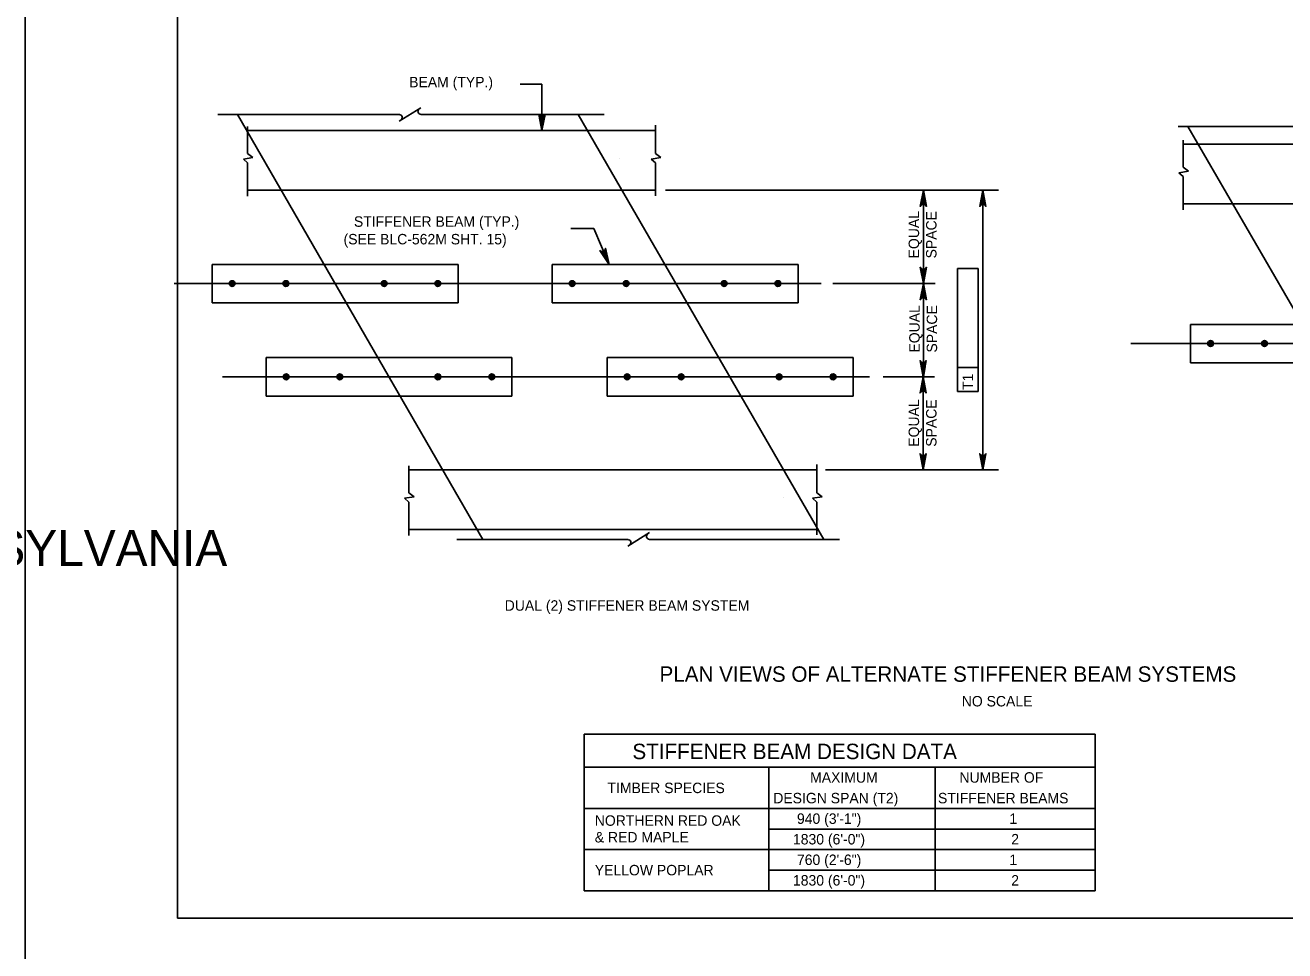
# Model space of a CAD drawing. Extents: x -13 to 81, y -176 to 0.
# Drawn here: x 34 to 48.46, y -131.62 to -121 of the extents above; entities that cross this region are included whole.
import ezdxf

# ---------------------------------------------------------------- set-up
doc = ezdxf.new("R2010")
doc.units = 0
for name, color, linetype in [('Level 1', 7, 'Continuous'), ('Level 10', 7, 'Continuous'), ('Level 2', 7, 'Continuous'), ('Level 3', 7, 'Continuous'), ('Level 4', 7, 'Continuous'), ('Level 63', 7, 'Continuous'), ('Level 8', 7, 'Continuous')]:
    doc.layers.add(name, color=color, linetype=linetype)

msp = doc.modelspace()

# ---------------------------------------------------------------- linework, layer by layer
at = {"layer": 'Level 1'}
msp.add_lwpolyline([(35.75, -131.25), (67.25, -131.25), (67.25, -110.75), (35.75, -110.75)], close=True, dxfattribs=at)
at = {"layer": 'Level 10'}
for p, q in [((40.418, -129.137), (40.418, -130.935)), ((40.418, -129.137), (46.284, -129.137)), ((46.284, -129.137), (46.284, -130.935)), ((40.418, -129.518), (46.284, -129.518)), ((42.537, -129.518), (42.537, -130.935)), ((44.448, -129.518), (44.448, -130.935)), ((40.418, -129.991), (46.284, -129.991)), ((42.537, -130.227), (46.284, -130.227)), ((40.418, -130.463), (46.284, -130.463)), ((42.537, -130.699), (46.284, -130.699)), ((40.418, -130.935), (46.284, -130.935))]:
    msp.add_line(p, q, dxfattribs=at)
at = {"layer": 'Level 2'}
for p, q in [((36.436, -122.025), (39.255, -126.903)), ((40.349, -122.025), (43.169, -126.903)), ((47.349, -122.161), (50.221, -127.129))]:
    msp.add_line(p, q, dxfattribs=at)
at = {"layer": 'Level 3'}
for p, q in [((38.296, -122.025), (36.213, -122.025)), ((38.542, -121.947), (38.295, -122.102)), ((40.646, -122.025), (38.544, -122.025)), ((36.554, -122.471), (36.554, -122.162)), ((41.237, -122.471), (41.237, -122.148)), ((49.318, -122.161), (47.235, -122.161)), ((41.237, -122.21), (36.554, -122.21)), ((47.292, -122.628), (47.292, -122.319)), ((36.615, -122.519), (36.554, -122.471)), ((41.298, -122.519), (41.237, -122.471)), ((51.975, -122.367), (47.292, -122.367)), ((36.505, -122.536), (36.615, -122.519)), ((36.554, -122.58), (36.505, -122.536)), ((36.554, -122.964), (36.554, -122.58)), ((41.188, -122.536), (41.298, -122.519)), ((41.237, -122.58), (41.188, -122.536)), ((41.237, -122.957), (41.237, -122.58)), ((47.244, -122.693), (47.354, -122.676)), ((47.292, -122.737), (47.244, -122.693)), ((47.354, -122.676), (47.292, -122.628)), ((47.292, -123.121), (47.292, -122.737)), ((36.554, -122.895), (41.237, -122.895)), ((47.292, -123.052), (51.975, -123.052)), ((38.969, -123.746), (36.146, -123.746)), ((36.146, -123.746), (36.146, -124.187)), ((38.969, -123.746), (38.969, -124.187)), ((42.872, -123.746), (40.049, -123.746)), ((40.049, -123.746), (40.049, -124.187)), ((42.872, -123.746), (42.872, -124.187)), ((41.464, -123.965), (41.464, -123.965)), ((38.969, -124.187), (36.146, -124.187)), ((42.872, -124.187), (40.049, -124.187)), ((50.201, -124.434), (47.378, -124.434)), ((47.378, -124.434), (47.378, -124.875)), ((39.588, -124.816), (36.765, -124.816)), ((36.765, -124.816), (36.765, -125.257)), ((39.588, -124.816), (39.588, -125.257)), ((40.682, -124.816), (40.682, -125.257)), ((43.505, -124.816), (40.682, -124.816)), ((43.505, -124.816), (43.505, -125.257)), ((50.201, -124.875), (47.378, -124.875)), ((42.096, -125.035), (42.096, -125.035)), ((39.588, -125.257), (36.765, -125.257)), ((43.505, -125.257), (40.682, -125.257)), ((38.405, -126.367), (38.405, -126.058)), ((43.088, -126.367), (43.088, -126.043)), ((43.088, -126.105), (38.405, -126.105)), ((38.466, -126.414), (38.405, -126.367)), ((43.149, -126.414), (43.088, -126.367)), ((38.356, -126.431), (38.466, -126.414)), ((38.405, -126.475), (38.356, -126.431)), ((38.405, -126.859), (38.405, -126.475)), ((43.039, -126.431), (43.149, -126.414)), ((43.088, -126.475), (43.039, -126.431)), ((43.088, -126.852), (43.088, -126.475)), ((38.405, -126.79), (43.088, -126.79)), ((40.92, -126.903), (38.954, -126.903)), ((41.166, -126.825), (40.92, -126.98)), ((43.348, -126.903), (41.169, -126.903))]:
    msp.add_line(p, q, dxfattribs=at)
for centre, radius in [((36.376, -123.966), 0.0333), ((36.376, -123.966), 0.0295), ((36.376, -123.966), 0.025), ((36.376, -123.966), 0.0167), ((36.376, -123.966), 0.00833), ((36.994, -123.966), 0.0333), ((36.994, -123.966), 0.0295), ((36.994, -123.966), 0.025), ((36.994, -123.966), 0.0167), ((36.994, -123.966), 0.00833), ((38.12, -123.966), 0.0333), ((38.12, -123.966), 0.0295), ((38.12, -123.966), 0.025), ((38.12, -123.966), 0.0167), ((38.12, -123.966), 0.00833), ((38.738, -123.966), 0.0333), ((38.738, -123.966), 0.0295), ((38.738, -123.966), 0.025), ((38.738, -123.966), 0.0167), ((38.738, -123.966), 0.00833), ((40.28, -123.966), 0.0333), ((40.28, -123.966), 0.0295), ((40.28, -123.966), 0.025), ((40.28, -123.966), 0.0167), ((40.28, -123.966), 0.00833), ((40.898, -123.966), 0.0333), ((40.898, -123.966), 0.0295), ((40.898, -123.966), 0.025), ((40.898, -123.966), 0.0167), ((40.898, -123.966), 0.00833), ((42.024, -123.966), 0.0333), ((42.024, -123.966), 0.0295), ((42.024, -123.966), 0.025), ((42.024, -123.966), 0.0167), ((42.024, -123.966), 0.00833), ((42.642, -123.966), 0.0333), ((42.642, -123.966), 0.0295), ((42.642, -123.966), 0.025), ((42.642, -123.966), 0.0167), ((42.642, -123.966), 0.00833), ((47.609, -124.654), 0.0333), ((47.609, -124.654), 0.0295), ((47.609, -124.654), 0.025), ((47.609, -124.654), 0.0167), ((47.609, -124.654), 0.00833), ((48.227, -124.654), 0.0333), ((48.227, -124.654), 0.0295), ((48.227, -124.654), 0.025), ((48.227, -124.654), 0.0167), ((48.227, -124.654), 0.00833), ((36.995, -125.036), 0.0333), ((36.995, -125.036), 0.0295), ((36.995, -125.036), 0.025), ((36.995, -125.036), 0.0167), ((36.995, -125.036), 0.00833), ((37.613, -125.036), 0.0333), ((37.613, -125.036), 0.0295), ((37.613, -125.036), 0.025), ((37.613, -125.036), 0.0167), ((37.613, -125.036), 0.00833), ((38.739, -125.036), 0.0333), ((38.739, -125.036), 0.0295), ((38.739, -125.036), 0.025), ((38.739, -125.036), 0.0167), ((38.739, -125.036), 0.00833), ((39.358, -125.036), 0.0333), ((39.358, -125.036), 0.0295), ((39.358, -125.036), 0.025), ((39.358, -125.036), 0.0167), ((39.358, -125.036), 0.00833), ((40.912, -125.036), 0.0333), ((40.912, -125.036), 0.0295), ((40.912, -125.036), 0.025), ((40.912, -125.036), 0.0167), ((40.912, -125.036), 0.00833), ((41.53, -125.036), 0.0333), ((41.53, -125.036), 0.0295), ((41.53, -125.036), 0.025), ((41.53, -125.036), 0.0167), ((41.53, -125.036), 0.00833), ((42.656, -125.036), 0.0333), ((42.656, -125.036), 0.0295), ((42.656, -125.036), 0.025), ((42.656, -125.036), 0.0167), ((42.656, -125.036), 0.00833), ((43.274, -125.036), 0.0333), ((43.274, -125.036), 0.0295), ((43.274, -125.036), 0.025), ((43.274, -125.036), 0.0167), ((43.274, -125.036), 0.00833)]:
    msp.add_circle(centre, radius, dxfattribs=at)
for centre, start, end in [((38.292, -122.061), 302.1328, 84.6714), ((38.545, -121.988), 120, 270), ((40.917, -126.939), 302.1328, 84.6714), ((41.169, -126.867), 120, 270)]:
    msp.add_arc(centre, 0.0364, start, end, dxfattribs=at)
at = {"layer": 'Level 4'}
for p, q in [((39.933, -121.677), (39.683, -121.677)), ((41.349, -122.895), (44.757, -122.895)), ((43.644, -122.895), (45.174, -122.895)), ((43.797, -122.895), (44.4, -122.895)), ((44.311, -122.895), (44.311, -123.965)), ((44.994, -122.895), (44.994, -126.105)), ((40.53, -123.333), (40.264, -123.333)), ((44.703, -123.793), (44.939, -123.793)), ((44.703, -124.906), (44.703, -123.793)), ((44.939, -123.793), (44.939, -125.205)), ((43.138, -123.965), (35.712, -123.965)), ((44.446, -123.965), (43.271, -123.965)), ((44.311, -123.965), (44.311, -124.917)), ((53.983, -124.654), (46.692, -124.654)), ((44.703, -125.205), (44.703, -124.906)), ((44.939, -124.93), (44.703, -124.93)), ((43.692, -125.036), (36.267, -125.036)), ((44.438, -125.035), (43.851, -125.035)), ((44.308, -125.153), (44.308, -126.105)), ((44.939, -125.205), (44.703, -125.205)), ((43.186, -126.105), (45.174, -126.105)), ((44.049, -126.105), (44.384, -126.105))]:
    msp.add_line(p, q, dxfattribs=at)
for points in [[(39.933, -122.21), (39.933, -121.677)], [(39.933, -122.21), (39.968, -122.024), (39.958, -122.038), (39.946, -122.045), (39.933, -122.048), (39.921, -122.045), (39.908, -122.038), (39.898, -122.024), (39.933, -122.21), (39.908, -122.038), (39.921, -122.045), (39.933, -122.21), (39.933, -122.048), (39.946, -122.045), (39.933, -122.21), (39.958, -122.038)], [(44.311, -122.895), (44.276, -123.081), (44.286, -123.067), (44.298, -123.06), (44.311, -123.057), (44.323, -123.06), (44.336, -123.067), (44.346, -123.081), (44.311, -122.895), (44.336, -123.067), (44.323, -123.06), (44.311, -122.895), (44.311, -123.057), (44.298, -123.06), (44.311, -122.895), (44.286, -123.067)], [(44.994, -122.895), (44.959, -123.081), (44.969, -123.067), (44.982, -123.06), (44.994, -123.057), (45.007, -123.06), (45.019, -123.067), (45.029, -123.081), (44.994, -122.895), (45.019, -123.067), (45.007, -123.06), (44.994, -122.895), (44.994, -123.057), (44.982, -123.06), (44.994, -122.895), (44.969, -123.067)], [(40.703, -123.746), (40.53, -123.333)], [(40.703, -123.746), (40.663, -123.56), (40.659, -123.578), (40.651, -123.589), (40.64, -123.596), (40.628, -123.599), (40.613, -123.597), (40.598, -123.587), (40.703, -123.746), (40.613, -123.597), (40.628, -123.599), (40.703, -123.746), (40.64, -123.596), (40.651, -123.589), (40.703, -123.746), (40.659, -123.578)], [(44.311, -123.965), (44.346, -123.779), (44.336, -123.793), (44.323, -123.8), (44.311, -123.803), (44.298, -123.8), (44.286, -123.793), (44.276, -123.779), (44.311, -123.965), (44.286, -123.793), (44.298, -123.8), (44.311, -123.965), (44.311, -123.803), (44.323, -123.8), (44.311, -123.965), (44.336, -123.793)], [(44.311, -123.965), (44.346, -124.151), (44.336, -124.137), (44.323, -124.13), (44.311, -124.128), (44.298, -124.13), (44.286, -124.137), (44.276, -124.151), (44.311, -123.965), (44.286, -124.137), (44.298, -124.13), (44.311, -123.965), (44.311, -124.128), (44.323, -124.13), (44.311, -123.965), (44.336, -124.137)], [(44.308, -125.035), (44.343, -124.849), (44.334, -124.863), (44.321, -124.87), (44.308, -124.873), (44.296, -124.87), (44.283, -124.863), (44.274, -124.849), (44.308, -125.035), (44.283, -124.863), (44.296, -124.87), (44.308, -125.035), (44.308, -124.873), (44.321, -124.87), (44.308, -125.035), (44.334, -124.863)], [(44.308, -125.035), (44.343, -125.222), (44.334, -125.207), (44.321, -125.2), (44.308, -125.198), (44.296, -125.2), (44.283, -125.207), (44.274, -125.222), (44.308, -125.035), (44.283, -125.207), (44.296, -125.2), (44.308, -125.035), (44.308, -125.198), (44.321, -125.2), (44.308, -125.035), (44.334, -125.207)], [(44.308, -126.105), (44.343, -125.919), (44.334, -125.933), (44.321, -125.941), (44.308, -125.943), (44.296, -125.941), (44.283, -125.933), (44.274, -125.919), (44.308, -126.105), (44.283, -125.933), (44.296, -125.941), (44.308, -126.105), (44.308, -125.943), (44.321, -125.941), (44.308, -126.105), (44.334, -125.933)], [(44.994, -126.105), (45.029, -125.919), (45.019, -125.933), (45.007, -125.941), (44.994, -125.943), (44.982, -125.941), (44.969, -125.933), (44.959, -125.919), (44.994, -126.105), (44.969, -125.933), (44.982, -125.941), (44.994, -126.105), (44.994, -125.943), (45.007, -125.941), (44.994, -126.105), (45.019, -125.933)]]:
    msp.add_lwpolyline(points, dxfattribs=at)
for points in [[(39.933, -122.21), (39.932, -122.205), (39.935, -122.205)], [(40.703, -123.746), (40.7, -123.742), (40.702, -123.741)], [(44.331, -124.917), (44.291, -124.917), (44.311, -125.035)], [(44.328, -125.153), (44.289, -125.153), (44.308, -125.035)], [(44.328, -125.987), (44.289, -125.987), (44.308, -126.105)], [(45.014, -125.985), (44.974, -125.985), (44.994, -126.105)]]:
    msp.add_lwpolyline(points, close=True, dxfattribs=at)
at = {"layer": 'Level 63'}
msp.add_lwpolyline([(34, -132), (68, -132), (68, -110), (34, -110)], close=True, dxfattribs=at)
at = {"layer": 'Level 8'}
for p, q in [((40.825, -122.525), (40.825, -122.525)), ((40.826, -122.526), (40.826, -122.526)), ((41.464, -123.965), (41.464, -123.965)), ((42.096, -125.035), (42.096, -125.035)), ((42.708, -126.421), (42.708, -126.421))]:
    msp.add_line(p, q, dxfattribs=at)

# ---------------------------------------------------------------- texts
at = {"layer": 'Level 1'}
msp.add_text('COMMONWEALTH OF PENNSYLVANIA', height=0.41048, dxfattribs=at).set_placement((26.194, -127.207))
at = {"layer": 'Level 4'}
for s, height, p in [('BEAM (TYP.)', 0.12, (38.408, -121.713)), ('STIFFENER BEAM (TYP.)', 0.12, (37.774, -123.314)), ('(SEE BLC-562M SHT. 15)', 0.12, (37.655, -123.516)), ('DUAL (2) STIFFENER BEAM SYSTEM', 0.12, (39.505, -127.721)), ('PLAN VIEWS OF ALTERNATE STIFFENER BEAM SYSTEMS', 0.17717, (41.282, -128.537)), ('NO SCALE', 0.12, (44.752, -128.82)), ('STIFFENER BEAM DESIGN DATA', 0.17717, (40.971, -129.425)), ('TIMBER SPECIES', 0.12, (40.685, -129.815)), ('MAXIMUM', 0.12, (43.011, -129.695)), ('NUMBER OF ', 0.12, (44.725, -129.695)), ('DESIGN SPAN (T2)', 0.12, (42.588, -129.932)), ('STIFFENER BEAMS', 0.12, (44.479, -129.932)), ('NORTHERN RED OAK', 0.12, (40.539, -130.19)), ('940 (3\'-1")', 0.12, (42.86, -130.168)), ('1', 0.12, (45.299, -130.168)), ('& RED MAPLE', 0.12, (40.539, -130.381)), ('1830 (6\'-0")', 0.12, (42.814, -130.404)), ('2', 0.12, (45.32, -130.404)), ('760 (2\'-6")', 0.12, (42.86, -130.64)), ('1', 0.12, (45.299, -130.64)), ('YELLOW POPLAR', 0.12, (40.539, -130.759)), ('1830 (6\'-0")', 0.12, (42.814, -130.876)), ('2', 0.12, (45.32, -130.876))]:
    msp.add_text(s, height=height, dxfattribs=at).set_placement(p)
msp.add_text('T1', height=0.12, rotation=90, dxfattribs=at).set_placement((44.882, -125.188))
at = {"layer": 'Level 8'}
for s, p in [('EQUAL ', (44.262, -123.677)), ('SPACE', (44.462, -123.677)), ('EQUAL ', (44.269, -124.758)), ('SPACE', (44.469, -124.758)), ('EQUAL ', (44.262, -125.839)), ('SPACE', (44.462, -125.839))]:
    msp.add_text(s, height=0.12, rotation=89.9708, dxfattribs=at).set_placement(p)

doc.saveas('drawing.dxf')
